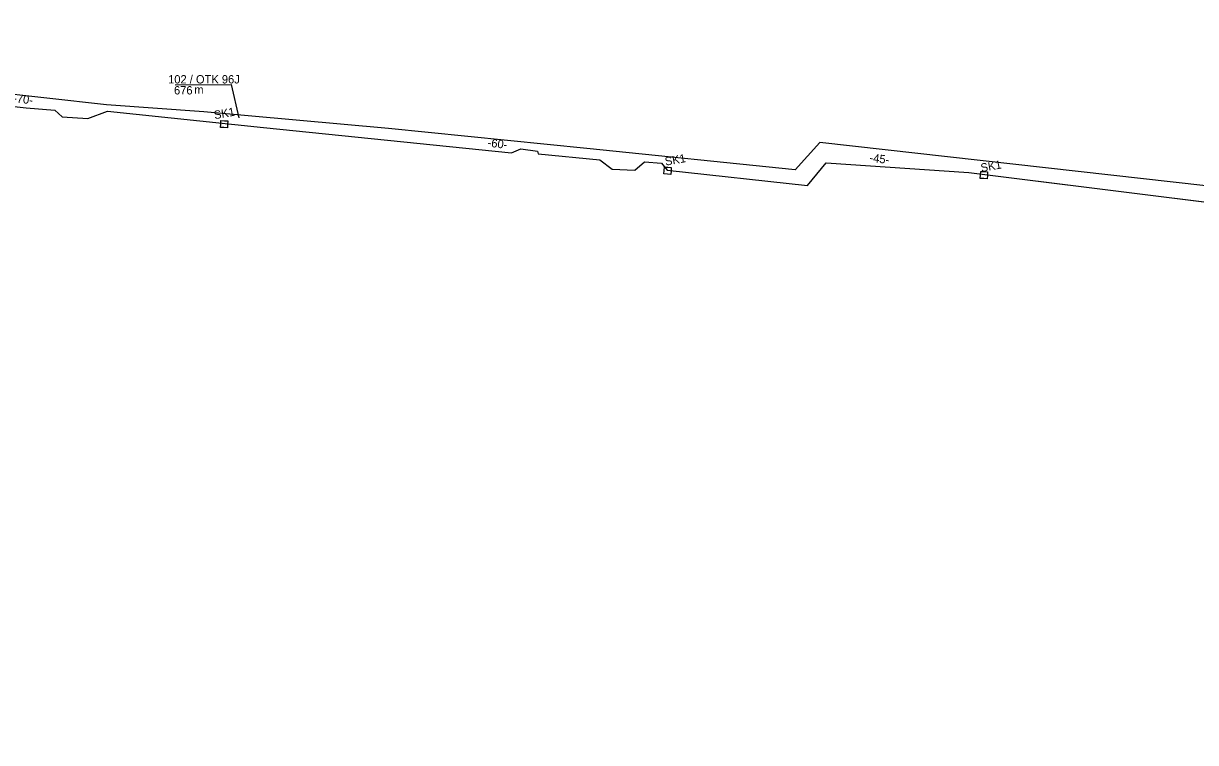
# Model space of a CAD drawing. Extents: x 6494530 to 6506885, y 5884901 to 5892312.
# Drawn here: x 6501025.5 to 6501177.2, y 5887367.6 to 5887460.7 of the extents above; entities that cross this region are included whole.
import ezdxf

# ---------------------------------------------------------------- set-up
doc = ezdxf.new("R2010")
doc.units = 0
for name, color, linetype in [('kabel W KANALIZACJI ISTN', 7, 'Continuous'), ('opis kabla CCTV_OTK', 7, 'Continuous'), ('opis kabla otk', 7, 'Continuous'), ('studnie do wyrysu', 7, 'Continuous'), ('trasa kanalizacji do wyrysu', 7, 'Continuous')]:
    doc.layers.add(name, color=color, linetype=linetype)

# ---------------------------------------------------------------- blocks, each defined once
blk = doc.blocks.new('ELARM2_43')
at = {"layer": 'studnie do wyrysu'}
blk.add_lwpolyline([(0, 0.45), (0.45, 0.45), (0.45, 0), (0.45, -0.45), (0, -0.45), (-0.45, -0.45), (-0.45, 0), (-0.45, 0.45)], close=True, dxfattribs=at)

msp = doc.modelspace()

# ---------------------------------------------------------------- linework, layer by layer
at = {"layer": 'kabel W KANALIZACJI ISTN'}
msp.add_lwpolyline([(6501492.98, 5887378.93), (6501481.99, 5887380.25), (6501473.69, 5887382.45), (6501462.45, 5887377.03), (6501452.4, 5887379.87), (6501448.25, 5887367.64), (6501367.44, 5887392.76), (6501297.54, 5887410.78), (6501228.74, 5887417.11), (6501229.07, 5887434.91), (6501182.72, 5887439.18), (6501128.55, 5887445.26), (6501125.35, 5887441.74), (6501098.4, 5887444.52), (6501072.74, 5887447.09), (6501048.84, 5887449.26), (6501036.27, 5887450.14), (6501020.76, 5887451.88), (6501013.69, 5887454.78), (6500973.89, 5887459.3), (6500959.6, 5887460.69), (6500954.67, 5887460.64)], dxfattribs=at)
at = {"layer": 'opis kabla otk'}
msp.add_lwpolyline([(6501045.14, 5887452.76), (6501052.37, 5887452.79), (6501053.38, 5887448.49)], dxfattribs=at)
at = {"layer": 'trasa kanalizacji do wyrysu'}
for points in [[(6500971.36, 5887458.25), (6501013.82, 5887453.64), (6501019.2, 5887450.48), (6501025.84, 5887449.75)], [(6501025.84, 5887449.75), (6501029.55, 5887449.46), (6501030.52, 5887448.62), (6501033.85, 5887448.4), (6501036.39, 5887449.33), (6501056.56, 5887447.2), (6501088.64, 5887443.95), (6501089.88, 5887444.44), (6501092.01, 5887444.18), (6501092.1, 5887443.82), (6501100.1, 5887443.02), (6501101.7, 5887441.82), (6501104.59, 5887441.69), (6501105.87, 5887442.8), (6501108.05, 5887442.62), (6501108.81, 5887441.69), (6501126.93, 5887439.73), (6501129.38, 5887442.66), (6501147.81, 5887441.42), (6501200.37, 5887434.85)], [(6501025.84, 5887449.75), (6501029.55, 5887449.46), (6501030.53, 5887448.62), (6501033.86, 5887448.4), (6501036.39, 5887449.33), (6501056.56, 5887447.2), (6501088.64, 5887443.95), (6501089.88, 5887444.44), (6501092.02, 5887444.18), (6501092.11, 5887443.82), (6501100.1, 5887443.02), (6501101.7, 5887441.82), (6501104.59, 5887441.69), (6501105.88, 5887442.8), (6501108.06, 5887442.62), (6501108.81, 5887441.69), (6501126.94, 5887439.73), (6501129.38, 5887442.66), (6501147.82, 5887441.42), (6501200.38, 5887434.85)], [(6501025.84, 5887449.75), (6501029.55, 5887449.46), (6501030.53, 5887448.62), (6501033.86, 5887448.4), (6501036.39, 5887449.33), (6501056.56, 5887447.2), (6501088.64, 5887443.95), (6501089.88, 5887444.44), (6501092.02, 5887444.18), (6501092.11, 5887443.82), (6501100.1, 5887443.02), (6501101.7, 5887441.82), (6501104.59, 5887441.69), (6501105.88, 5887442.8), (6501108.06, 5887442.62), (6501108.81, 5887441.69), (6501126.94, 5887439.73), (6501129.38, 5887442.66), (6501147.82, 5887441.42), (6501200.38, 5887434.85)], [(6501025.84, 5887449.75), (6501029.55, 5887449.46), (6501030.53, 5887448.62), (6501033.86, 5887448.4), (6501036.39, 5887449.33), (6501056.56, 5887447.2), (6501088.64, 5887443.95), (6501089.88, 5887444.44), (6501092.02, 5887444.18), (6501092.11, 5887443.82), (6501100.1, 5887443.02), (6501101.7, 5887441.82), (6501104.59, 5887441.69), (6501105.88, 5887442.8), (6501108.06, 5887442.62), (6501108.81, 5887441.69), (6501126.94, 5887439.73), (6501129.38, 5887442.66), (6501147.82, 5887441.42), (6501200.38, 5887434.85)], [(6501025.84, 5887449.75), (6501029.55, 5887449.46), (6501030.53, 5887448.62), (6501033.86, 5887448.4), (6501036.39, 5887449.33), (6501056.56, 5887447.2), (6501088.64, 5887443.95), (6501089.88, 5887444.44), (6501092.02, 5887444.18), (6501092.11, 5887443.82), (6501100.1, 5887443.02), (6501101.7, 5887441.82), (6501104.59, 5887441.69), (6501105.88, 5887442.8), (6501108.06, 5887442.62), (6501108.81, 5887441.69), (6501126.94, 5887439.73), (6501129.38, 5887442.66), (6501147.82, 5887441.42), (6501200.38, 5887434.85)], [(6501025.84, 5887449.75), (6501029.55, 5887449.46), (6501030.53, 5887448.62), (6501033.86, 5887448.4), (6501036.39, 5887449.33), (6501056.56, 5887447.2), (6501088.64, 5887443.95), (6501089.88, 5887444.44), (6501092.02, 5887444.18), (6501092.11, 5887443.82), (6501100.1, 5887443.02), (6501101.7, 5887441.82), (6501104.59, 5887441.69), (6501105.88, 5887442.8), (6501108.06, 5887442.62), (6501108.81, 5887441.69), (6501126.94, 5887439.73), (6501129.38, 5887442.66), (6501147.82, 5887441.42), (6501200.38, 5887434.85)], [(6501025.84, 5887449.75), (6501029.55, 5887449.46), (6501030.52, 5887448.62), (6501033.85, 5887448.4), (6501036.39, 5887449.33), (6501056.56, 5887447.2), (6501088.64, 5887443.95), (6501089.88, 5887444.44), (6501092.01, 5887444.18), (6501092.1, 5887443.82), (6501100.1, 5887443.02), (6501101.7, 5887441.82), (6501104.59, 5887441.69), (6501105.87, 5887442.8), (6501108.05, 5887442.62), (6501108.81, 5887441.69), (6501126.93, 5887439.73), (6501129.38, 5887442.66), (6501147.81, 5887441.42), (6501200.37, 5887434.85)]]:
    msp.add_lwpolyline(points, dxfattribs=at)

# ---------------------------------------------------------------- block references
at = {"layer": 'studnie do wyrysu', "rotation": -3.8347981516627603}
for p in [(6501051.48, 5887447.65), (6501108.85, 5887441.63), (6501149.78, 5887441.06)]:
    msp.add_blockref('ELARM2_43', p, dxfattribs=at)

# ---------------------------------------------------------------- texts
at = {"layer": 'opis kabla CCTV_OTK'}
for s, height, p in [('102 / OTK 96J', 1.075, (6501044.23, 5887452.92)), ('676', 1.075, (6501044.99, 5887451.5)), ('m', 1.07, (6501047.62, 5887451.59))]:
    msp.add_text(s, height=height, dxfattribs=at).set_placement(p)
at = {"layer": 'studnie do wyrysu'}
for p in [(6501050.25, 5887448.29), (6501108.6, 5887442.28), (6501149.45, 5887441.46)]:
    msp.add_text('SK1', height=1.075, rotation=10.0891, dxfattribs=at).set_placement(p)
at = {"layer": 'trasa kanalizacji do wyrysu'}
for s, p in [('-70-', (6501024.13, 5887450.51)), ('-60-', (6501085.52, 5887444.75)), ('-45-', (6501134.93, 5887442.8))]:
    msp.add_text(s, height=1.075, rotation=353.1751, dxfattribs=at).set_placement(p)

doc.saveas('drawing.dxf')
